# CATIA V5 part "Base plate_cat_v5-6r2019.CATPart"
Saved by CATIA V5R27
Part number: Base Plate
Bounding box of the stored display mesh (mm): x -10 to 10, y 0 to 144, z 0 to 6
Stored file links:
  E:\_Deepak\2017_Deepak\CATIA\Resources\Tutorial Files\Tutorials\c16_catia_v5_6r2016_tut\Bench vice\Base plate_cat_v5-6r2016.CATPart
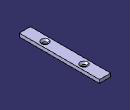
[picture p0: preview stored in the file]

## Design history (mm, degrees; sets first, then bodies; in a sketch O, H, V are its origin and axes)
Body1 (main body)
  Sketch1 on zx-plane, origin (0, 0, 0), H (-1, 0, 0), V (0, 0, 1)
    point P1 (-10, 0)
    line L1 (-10, 0) -> (10, 0)
    line L2 (10, 0) -> (10, 6)
    line L3 (10, 6) -> (-10, 6)
    line L4 (-10, 6) -> (-10, 0)
    length L3 = 20
    length L2 = 6
    distance V L2 = 10
    coincidence: P1 H
    horizontal: L1 H, L3 H
    vertical: L2 V, L4 V
  Pad1: profile Sketch1, direction (0, 1, 0), length 144
  Sketch2 on face of Pad1, origin (-6.0071, 115.251, 6), H (1, 0, 0), V (0, 1, 0)
    point P1 (6.0071, -9.251)
    reference projected line E1 (-3.9929, -115.251) -> (-3.9929, 28.749) from edge of Pad1
    reference projected line E2 (16.0071, 28.749) -> (-3.9929, 28.749) from edge of Pad1
    distance E1 P1 = 10
    distance E2 P1 = 38
  Hole1: placed by Sketch2, at (0, 106, 6) direction (0, 0, -1), diameter 7, through (limit type 6), countersink depth 3, countersink angle 90
  RectPattern1: of Hole1, direction 1 instances 2, spacing 70, along edge of Pad1 reversed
